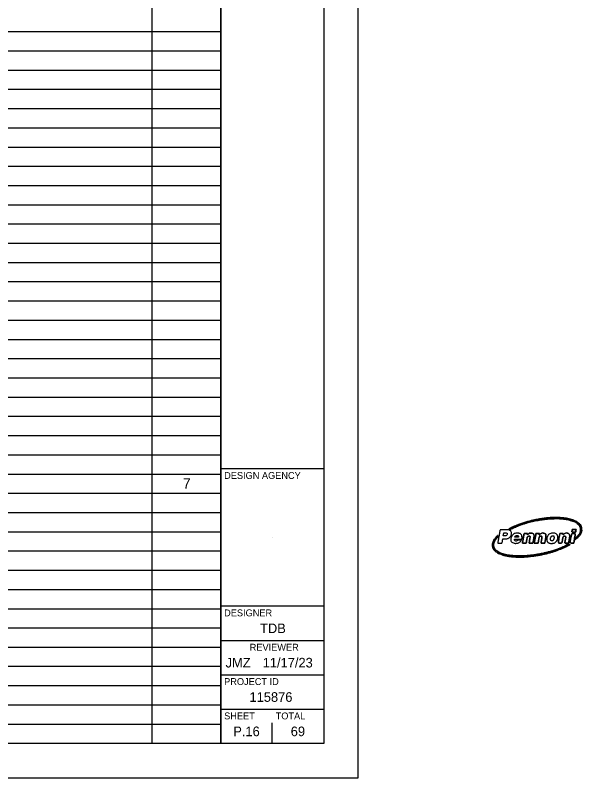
# Model space of a CAD drawing. Extents: x -31.7 to 37.3, y 0 to 22.
# Drawn here: x 29.01 to 37.25, y 0 to 11.1 of the extents above; entities that cross this region are included whole.
import ezdxf

# ---------------------------------------------------------------- set-up
doc = ezdxf.new("R2010")
doc.units = 0
for name, color, linetype in [('SH_Border', 7, 'Continuous'), ('SH_Cut_Line', 7, 'Continuous'), ('SH_Data', 7, 'Continuous'), ('SH_Text', 7, 'Continuous')]:
    doc.layers.add(name, color=color, linetype=linetype)

msp = doc.modelspace()

# ---------------------------------------------------------------- linework, layer by layer
at = {"layer": 'SH_Border'}
for p, q in [((32, 0.5), (32, 21.5)), ((32, 4.5), (33.5, 4.5)), ((36.333, 3.503), (36.282, 3.503)), ((32, 2.5), (33.5, 2.5)), ((32, 2), (33.5, 2)), ((32, 1.5), (33.5, 1.5)), ((32, 1), (33.5, 1))]:
    msp.add_line(p, q, dxfattribs=at)
msp.add_lwpolyline([(1.5, 21.5), (33.5, 21.5), (33.5, 0.5), (1.5, 0.5)], close=True, dxfattribs=at)
for points, degree in [([(36.192, 3.621), (36.198, 3.619), (36.204, 3.616), (36.211, 3.615), (36.213, 3.614), (36.215, 3.614), (36.217, 3.615), (36.246, 3.629), (36.274, 3.643), (36.303, 3.655), (36.345, 3.673), (36.387, 3.688), (36.43, 3.701), (36.472, 3.714), (36.514, 3.725), (36.557, 3.734), (36.597, 3.743), (36.637, 3.751), (36.678, 3.756), (36.709, 3.76), (36.741, 3.764), (36.774, 3.767), (36.799, 3.769), (36.824, 3.77), (36.849, 3.771), (36.904, 3.772), (36.959, 3.77), (37.014, 3.762), (37.044, 3.758), (37.073, 3.752), (37.101, 3.742), (37.137, 3.731), (37.171, 3.717), (37.199, 3.691), (37.214, 3.678), (37.225, 3.661), (37.231, 3.641), (37.235, 3.624), (37.237, 3.607), (37.234, 3.589), (37.23, 3.569), (37.221, 3.552), (37.208, 3.536), (37.196, 3.521), (37.182, 3.508), (37.167, 3.495), (37.166, 3.494), (37.164, 3.492), (37.164, 3.49), (37.162, 3.485), (37.161, 3.479), (37.16, 3.473), (37.16, 3.471), (37.16, 3.469), (37.159, 3.465), (37.183, 3.485), (37.206, 3.505), (37.225, 3.529), (37.234, 3.54), (37.241, 3.553), (37.246, 3.566), (37.253, 3.585), (37.253, 3.604), (37.251, 3.623), (37.247, 3.658), (37.232, 3.685), (37.205, 3.708), (37.182, 3.728), (37.154, 3.741), (37.125, 3.752), (37.088, 3.766), (37.049, 3.774), (37.01, 3.779), (36.975, 3.784), (36.94, 3.787), (36.905, 3.788), (36.848, 3.789), (36.792, 3.787), (36.736, 3.781), (36.705, 3.777), (36.674, 3.773), (36.643, 3.768), (36.598, 3.761), (36.553, 3.752), (36.509, 3.74), (36.449, 3.725), (36.389, 3.707), (36.331, 3.684), (36.29, 3.669), (36.25, 3.651), (36.211, 3.631), (36.205, 3.628), (36.199, 3.625), (36.192, 3.621)], 3), ([(36.192, 3.621), (36.199, 3.625), (36.205, 3.628), (36.211, 3.631), (36.25, 3.651), (36.29, 3.669), (36.331, 3.684), (36.389, 3.707), (36.449, 3.725), (36.509, 3.74), (36.553, 3.752), (36.598, 3.761), (36.643, 3.768), (36.674, 3.773), (36.705, 3.777), (36.736, 3.781), (36.792, 3.787), (36.848, 3.789), (36.905, 3.788), (36.94, 3.787), (36.975, 3.784), (37.01, 3.779), (37.049, 3.774), (37.088, 3.766), (37.125, 3.752), (37.154, 3.741), (37.182, 3.728), (37.205, 3.708), (37.232, 3.685), (37.247, 3.658), (37.251, 3.623), (37.253, 3.604), (37.253, 3.585), (37.246, 3.566), (37.241, 3.553), (37.234, 3.54), (37.225, 3.529), (37.206, 3.505), (37.183, 3.485), (37.159, 3.465), (37.16, 3.469), (37.16, 3.471), (37.16, 3.473), (37.161, 3.479), (37.162, 3.485), (37.164, 3.49), (37.164, 3.492), (37.166, 3.494), (37.167, 3.495), (37.182, 3.508), (37.196, 3.521), (37.208, 3.536), (37.221, 3.552), (37.23, 3.569), (37.234, 3.589), (37.237, 3.607), (37.235, 3.624), (37.231, 3.641), (37.225, 3.661), (37.214, 3.678), (37.199, 3.691), (37.171, 3.717), (37.137, 3.731), (37.101, 3.742), (37.073, 3.752), (37.044, 3.758), (37.014, 3.762), (36.959, 3.77), (36.904, 3.772), (36.849, 3.771), (36.824, 3.77), (36.799, 3.769), (36.774, 3.767), (36.741, 3.764), (36.709, 3.76), (36.678, 3.756), (36.637, 3.751), (36.597, 3.743), (36.557, 3.734), (36.514, 3.725), (36.472, 3.714), (36.43, 3.701), (36.387, 3.688), (36.345, 3.673), (36.303, 3.655), (36.274, 3.643), (36.246, 3.629), (36.217, 3.615), (36.215, 3.614), (36.213, 3.614), (36.211, 3.615), (36.204, 3.616), (36.198, 3.619), (36.192, 3.621)], 3), ([(36.203, 3.602), (36.19, 3.608), (36.177, 3.61), (36.163, 3.61), (36.131, 3.611), (36.1, 3.61), (36.068, 3.61), (36.066, 3.61), (36.065, 3.61), (36.065, 3.608), (36.061, 3.586), (36.057, 3.565), (36.053, 3.543), (36.047, 3.509), (36.041, 3.474), (36.035, 3.439), (36.034, 3.432), (36.033, 3.424), (36.031, 3.417)], 3), ([(36.105, 3.477), (36.112, 3.477), (36.119, 3.477), (36.126, 3.477), (36.139, 3.477), (36.152, 3.477), (36.165, 3.48), (36.181, 3.483), (36.196, 3.49), (36.208, 3.502), (36.223, 3.518), (36.229, 3.537), (36.23, 3.559), (36.23, 3.578), (36.221, 3.593), (36.203, 3.602)], 3), ([(36.112, 3.522), (36.115, 3.536), (36.117, 3.55), (36.12, 3.563), (36.12, 3.564), (36.121, 3.565), (36.122, 3.565), (36.133, 3.565), (36.145, 3.567), (36.156, 3.563), (36.167, 3.56), (36.17, 3.554), (36.168, 3.543)], 3), ([(36.384, 3.508), (36.38, 3.533), (36.367, 3.55), (36.343, 3.557), (36.33, 3.562), (36.317, 3.562), (36.303, 3.561), (36.281, 3.558), (36.262, 3.549), (36.247, 3.532), (36.233, 3.517), (36.225, 3.5), (36.222, 3.479), (36.219, 3.45), (36.232, 3.426), (36.261, 3.417), (36.277, 3.412), (36.293, 3.411), (36.309, 3.414), (36.327, 3.416), (36.343, 3.422), (36.357, 3.434), (36.365, 3.441), (36.371, 3.449), (36.376, 3.459)], 3), ([(36.39, 3.416), (36.391, 3.415), (36.391, 3.415), (36.392, 3.415), (36.409, 3.415), (36.426, 3.415), (36.443, 3.415), (36.445, 3.415), (36.446, 3.416), (36.446, 3.418), (36.448, 3.426), (36.449, 3.435), (36.45, 3.443), (36.453, 3.46), (36.456, 3.478), (36.46, 3.495), (36.462, 3.505), (36.467, 3.513), (36.477, 3.515), (36.49, 3.519), (36.503, 3.516), (36.501, 3.497), (36.499, 3.482), (36.497, 3.468), (36.494, 3.454), (36.492, 3.441), (36.49, 3.428), (36.487, 3.416), (36.488, 3.415), (36.489, 3.415), (36.489, 3.415), (36.506, 3.415), (36.523, 3.415), (36.54, 3.415), (36.543, 3.415), (36.543, 3.416), (36.544, 3.419), (36.548, 3.442), (36.552, 3.466), (36.556, 3.49), (36.558, 3.502), (36.561, 3.515), (36.559, 3.527), (36.557, 3.543), (36.547, 3.554), (36.532, 3.558), (36.51, 3.564), (36.49, 3.56), (36.473, 3.545), (36.469, 3.542), (36.466, 3.538), (36.462, 3.535), (36.463, 3.542), (36.464, 3.549), (36.465, 3.557), (36.449, 3.557), (36.433, 3.557), (36.417, 3.556), (36.416, 3.556), (36.415, 3.555), (36.414, 3.554), (36.413, 3.55), (36.413, 3.545), (36.412, 3.541), (36.407, 3.511), (36.401, 3.48), (36.396, 3.45), (36.394, 3.438), (36.392, 3.427), (36.39, 3.416)], 3), ([(36.39, 3.416), (36.392, 3.427), (36.394, 3.438), (36.396, 3.45), (36.401, 3.48), (36.407, 3.511), (36.412, 3.541), (36.413, 3.545), (36.413, 3.55), (36.414, 3.554), (36.415, 3.555), (36.416, 3.556), (36.417, 3.556), (36.433, 3.557), (36.449, 3.557), (36.465, 3.557), (36.464, 3.549), (36.463, 3.542), (36.462, 3.535), (36.466, 3.538), (36.469, 3.542), (36.473, 3.545), (36.49, 3.56), (36.51, 3.564), (36.532, 3.558), (36.547, 3.554), (36.557, 3.543), (36.559, 3.527), (36.561, 3.515), (36.558, 3.502), (36.556, 3.49), (36.552, 3.466), (36.548, 3.442), (36.544, 3.419), (36.543, 3.416), (36.543, 3.415), (36.54, 3.415), (36.523, 3.415), (36.506, 3.415), (36.489, 3.415), (36.489, 3.415), (36.488, 3.415), (36.487, 3.416), (36.49, 3.428), (36.492, 3.441), (36.494, 3.454), (36.497, 3.468), (36.499, 3.482), (36.501, 3.497), (36.503, 3.516), (36.49, 3.519), (36.477, 3.515), (36.467, 3.513), (36.462, 3.505), (36.46, 3.495), (36.456, 3.478), (36.453, 3.46), (36.45, 3.443), (36.449, 3.435), (36.448, 3.426), (36.446, 3.418), (36.446, 3.416), (36.445, 3.415), (36.443, 3.415), (36.426, 3.415), (36.409, 3.415), (36.392, 3.415), (36.391, 3.415), (36.391, 3.415), (36.39, 3.416)], 3), ([(36.563, 3.416), (36.564, 3.415), (36.564, 3.415), (36.564, 3.415), (36.581, 3.415), (36.599, 3.415), (36.616, 3.415), (36.617, 3.415), (36.619, 3.417), (36.619, 3.418), (36.622, 3.435), (36.625, 3.452), (36.628, 3.469), (36.63, 3.479), (36.632, 3.49), (36.635, 3.5), (36.639, 3.513), (36.651, 3.519), (36.664, 3.516), (36.67, 3.515), (36.673, 3.511), (36.674, 3.505), (36.674, 3.502), (36.675, 3.499), (36.674, 3.496), (36.672, 3.485), (36.671, 3.473), (36.669, 3.462), (36.666, 3.447), (36.663, 3.431), (36.661, 3.416), (36.661, 3.415), (36.661, 3.415), (36.661, 3.415), (36.679, 3.415), (36.696, 3.415), (36.714, 3.415), (36.715, 3.415), (36.716, 3.417), (36.716, 3.418), (36.72, 3.441), (36.725, 3.463), (36.728, 3.485), (36.73, 3.497), (36.732, 3.509), (36.732, 3.522), (36.732, 3.537), (36.726, 3.55), (36.711, 3.556), (36.69, 3.564), (36.67, 3.562), (36.652, 3.55), (36.646, 3.545), (36.641, 3.54), (36.635, 3.535), (36.636, 3.543), (36.637, 3.549), (36.638, 3.557), (36.622, 3.557), (36.606, 3.557), (36.59, 3.557), (36.587, 3.557), (36.587, 3.555), (36.587, 3.553), (36.583, 3.529), (36.579, 3.505), (36.575, 3.481), (36.571, 3.46), (36.567, 3.438), (36.563, 3.416)], 3), ([(36.563, 3.416), (36.567, 3.438), (36.571, 3.46), (36.575, 3.481), (36.579, 3.505), (36.583, 3.529), (36.587, 3.553), (36.587, 3.555), (36.587, 3.557), (36.59, 3.557), (36.606, 3.557), (36.622, 3.557), (36.638, 3.557), (36.637, 3.549), (36.636, 3.543), (36.635, 3.535), (36.641, 3.54), (36.646, 3.545), (36.652, 3.55), (36.67, 3.562), (36.69, 3.564), (36.711, 3.556), (36.726, 3.55), (36.732, 3.537), (36.732, 3.522), (36.732, 3.509), (36.73, 3.497), (36.728, 3.485), (36.725, 3.463), (36.72, 3.441), (36.716, 3.418), (36.716, 3.417), (36.715, 3.415), (36.714, 3.415), (36.696, 3.415), (36.679, 3.415), (36.661, 3.415), (36.661, 3.415), (36.661, 3.415), (36.661, 3.416), (36.663, 3.431), (36.666, 3.447), (36.669, 3.462), (36.671, 3.473), (36.672, 3.485), (36.674, 3.496), (36.675, 3.499), (36.674, 3.502), (36.674, 3.505), (36.673, 3.511), (36.67, 3.515), (36.664, 3.516), (36.651, 3.519), (36.639, 3.513), (36.635, 3.5), (36.632, 3.49), (36.63, 3.479), (36.628, 3.469), (36.625, 3.452), (36.622, 3.435), (36.619, 3.418), (36.619, 3.417), (36.617, 3.415), (36.616, 3.415), (36.599, 3.415), (36.581, 3.415), (36.564, 3.415), (36.564, 3.415), (36.564, 3.415), (36.563, 3.416)], 3), ([(36.906, 3.508), (36.905, 3.53), (36.894, 3.545), (36.873, 3.554), (36.854, 3.562), (36.834, 3.562), (36.814, 3.558), (36.79, 3.553), (36.771, 3.541), (36.758, 3.52), (36.757, 3.518), (36.755, 3.515), (36.754, 3.513), (36.753, 3.511), (36.752, 3.509), (36.751, 3.507), (36.746, 3.496), (36.744, 3.484), (36.743, 3.472), (36.743, 3.47), (36.743, 3.467), (36.743, 3.465), (36.744, 3.457), (36.745, 3.45), (36.748, 3.444), (36.749, 3.443), (36.749, 3.441), (36.75, 3.44), (36.75, 3.439), (36.751, 3.438), (36.752, 3.437), (36.754, 3.434), (36.757, 3.43), (36.76, 3.427), (36.762, 3.426), (36.764, 3.424), (36.766, 3.423), (36.767, 3.422), (36.767, 3.422), (36.768, 3.422), (36.769, 3.421), (36.77, 3.42), (36.772, 3.42), (36.773, 3.419), (36.775, 3.418), (36.777, 3.417), (36.788, 3.412), (36.8, 3.411), (36.812, 3.41)], 3), ([(36.934, 3.556), (36.926, 3.509), (36.917, 3.462), (36.909, 3.415), (36.928, 3.415), (36.946, 3.415), (36.965, 3.415), (36.967, 3.43), (36.97, 3.444), (36.972, 3.458), (36.974, 3.471), (36.977, 3.484), (36.979, 3.496), (36.983, 3.51), (36.992, 3.517), (37.006, 3.517), (37.014, 3.516), (37.019, 3.511), (37.02, 3.503), (37.021, 3.5), (37.021, 3.497), (37.02, 3.494), (37.017, 3.475), (37.014, 3.456), (37.01, 3.437), (37.009, 3.43), (37.008, 3.423), (37.007, 3.415), (37.025, 3.415), (37.044, 3.415), (37.062, 3.415), (37.062, 3.417), (37.063, 3.418), (37.063, 3.419), (37.067, 3.44), (37.07, 3.462), (37.074, 3.483), (37.076, 3.497), (37.079, 3.51), (37.078, 3.525), (37.077, 3.541), (37.068, 3.553), (37.053, 3.558), (37.028, 3.565), (37.006, 3.559), (36.987, 3.541), (36.985, 3.539), (36.983, 3.537), (36.982, 3.535), (36.981, 3.535), (36.981, 3.535), (36.981, 3.536), (36.982, 3.542), (36.983, 3.549), (36.984, 3.556), (36.967, 3.556), (36.951, 3.556), (36.934, 3.556)], 3), ([(36.934, 3.556), (36.951, 3.556), (36.967, 3.556), (36.984, 3.556), (36.983, 3.549), (36.982, 3.542), (36.981, 3.536), (36.981, 3.535), (36.981, 3.535), (36.982, 3.535), (36.983, 3.537), (36.985, 3.539), (36.987, 3.541), (37.006, 3.559), (37.028, 3.565), (37.053, 3.558), (37.068, 3.553), (37.077, 3.541), (37.078, 3.525), (37.079, 3.51), (37.076, 3.497), (37.074, 3.483), (37.07, 3.462), (37.067, 3.44), (37.063, 3.419), (37.063, 3.418), (37.062, 3.417), (37.062, 3.415), (37.044, 3.415), (37.025, 3.415), (37.007, 3.415), (37.008, 3.423), (37.009, 3.43), (37.01, 3.437), (37.014, 3.456), (37.017, 3.475), (37.02, 3.494), (37.021, 3.497), (37.021, 3.5), (37.02, 3.503), (37.019, 3.511), (37.014, 3.516), (37.006, 3.517), (36.992, 3.517), (36.983, 3.51), (36.979, 3.496), (36.977, 3.484), (36.974, 3.471), (36.972, 3.458), (36.97, 3.444), (36.967, 3.43), (36.965, 3.415), (36.946, 3.415), (36.928, 3.415), (36.909, 3.415), (36.917, 3.462), (36.926, 3.509), (36.934, 3.556)], 3), ([(37.137, 3.417), (37.118, 3.417), (37.1, 3.417), (37.081, 3.417), (37.09, 3.464), (37.098, 3.51), (37.106, 3.557), (37.124, 3.557), (37.142, 3.557), (37.161, 3.557), (37.153, 3.51), (37.145, 3.464), (37.137, 3.417)], 3), ([(37.137, 3.417), (37.145, 3.464), (37.153, 3.51), (37.161, 3.557), (37.142, 3.557), (37.124, 3.557), (37.106, 3.557), (37.098, 3.51), (37.09, 3.464), (37.081, 3.417), (37.1, 3.417), (37.118, 3.417), (37.137, 3.417)], 3), ([(37.171, 3.615), (37.169, 3.603), (37.167, 3.591), (37.165, 3.578), (37.165, 3.577), (37.163, 3.576), (37.162, 3.576), (37.145, 3.576), (37.127, 3.576), (37.109, 3.576), (37.111, 3.586), (37.112, 3.595), (37.114, 3.604), (37.114, 3.606), (37.115, 3.609), (37.115, 3.611), (37.115, 3.615), (37.117, 3.615), (37.12, 3.615), (37.136, 3.615), (37.151, 3.615), (37.167, 3.615), (37.168, 3.615), (37.17, 3.615), (37.171, 3.615)], 3), ([(37.171, 3.615), (37.17, 3.615), (37.168, 3.615), (37.167, 3.615), (37.151, 3.615), (37.136, 3.615), (37.12, 3.615), (37.117, 3.615), (37.115, 3.615), (37.115, 3.611), (37.115, 3.609), (37.114, 3.606), (37.114, 3.604), (37.112, 3.595), (37.111, 3.586), (37.109, 3.576), (37.127, 3.576), (37.145, 3.576), (37.162, 3.576), (37.163, 3.576), (37.165, 3.577), (37.165, 3.578), (37.167, 3.591), (37.169, 3.603), (37.171, 3.615)], 3), ([(37.08, 3.392), (37.08, 3.392), (37.08, 3.393), (37.079, 3.393), (37.069, 3.393), (37.06, 3.393), (37.05, 3.393), (37.047, 3.393), (37.044, 3.392), (37.042, 3.391), (37.005, 3.372), (36.967, 3.355), (36.928, 3.34), (36.87, 3.317), (36.811, 3.298), (36.75, 3.283), (36.707, 3.271), (36.664, 3.262), (36.62, 3.254), (36.595, 3.25), (36.571, 3.246), (36.546, 3.242), (36.52, 3.239), (36.495, 3.236), (36.469, 3.234), (36.445, 3.232), (36.421, 3.23), (36.396, 3.23), (36.368, 3.229), (36.34, 3.228), (36.312, 3.229), (36.281, 3.231), (36.25, 3.233), (36.219, 3.236), (36.181, 3.24), (36.144, 3.248), (36.107, 3.259), (36.075, 3.269), (36.045, 3.282), (36.019, 3.302), (36.002, 3.314), (35.988, 3.329), (35.979, 3.348), (35.966, 3.374), (35.968, 3.4), (35.978, 3.427), (35.987, 3.45), (36.002, 3.47), (36.018, 3.488), (36.024, 3.494), (36.029, 3.5), (36.03, 3.509), (36.03, 3.514), (36.031, 3.52), (36.033, 3.526), (36.031, 3.525), (36.03, 3.525), (36.03, 3.524), (36.02, 3.514), (36.01, 3.505), (36.001, 3.494), (35.982, 3.472), (35.966, 3.448), (35.958, 3.419), (35.953, 3.402), (35.952, 3.385), (35.955, 3.368), (35.96, 3.341), (35.974, 3.319), (35.994, 3.301), (36.016, 3.28), (36.043, 3.266), (36.071, 3.254), (36.119, 3.235), (36.168, 3.225), (36.218, 3.219), (36.249, 3.216), (36.28, 3.214), (36.311, 3.212), (36.353, 3.211), (36.396, 3.211), (36.438, 3.215), (36.472, 3.217), (36.506, 3.221), (36.54, 3.225), (36.571, 3.229), (36.602, 3.234), (36.632, 3.239), (36.687, 3.249), (36.74, 3.261), (36.793, 3.276), (36.839, 3.289), (36.883, 3.304), (36.927, 3.321), (36.97, 3.338), (37.012, 3.356), (37.053, 3.377), (37.062, 3.382), (37.071, 3.387), (37.08, 3.392)], 3), ([(37.08, 3.392), (37.071, 3.387), (37.062, 3.382), (37.053, 3.377), (37.012, 3.356), (36.97, 3.338), (36.927, 3.321), (36.883, 3.304), (36.839, 3.289), (36.793, 3.276), (36.74, 3.261), (36.687, 3.249), (36.632, 3.239), (36.602, 3.234), (36.571, 3.229), (36.54, 3.225), (36.506, 3.221), (36.472, 3.217), (36.438, 3.215), (36.396, 3.211), (36.353, 3.211), (36.311, 3.212), (36.28, 3.214), (36.249, 3.216), (36.218, 3.219), (36.168, 3.225), (36.119, 3.235), (36.071, 3.254), (36.043, 3.266), (36.016, 3.28), (35.994, 3.301), (35.974, 3.319), (35.96, 3.341), (35.955, 3.368), (35.952, 3.385), (35.953, 3.402), (35.958, 3.419), (35.966, 3.448), (35.982, 3.472), (36.001, 3.494), (36.01, 3.505), (36.02, 3.514), (36.03, 3.524), (36.03, 3.525), (36.031, 3.525), (36.033, 3.526), (36.031, 3.52), (36.03, 3.514), (36.03, 3.509), (36.029, 3.5), (36.024, 3.494), (36.018, 3.488), (36.002, 3.47), (35.987, 3.45), (35.978, 3.427), (35.968, 3.4), (35.966, 3.374), (35.979, 3.348), (35.988, 3.329), (36.002, 3.314), (36.019, 3.302), (36.045, 3.282), (36.075, 3.269), (36.107, 3.259), (36.144, 3.248), (36.181, 3.24), (36.219, 3.236), (36.25, 3.233), (36.281, 3.231), (36.312, 3.229), (36.34, 3.228), (36.368, 3.229), (36.396, 3.23), (36.421, 3.23), (36.445, 3.232), (36.469, 3.234), (36.495, 3.236), (36.52, 3.239), (36.546, 3.242), (36.571, 3.246), (36.595, 3.25), (36.62, 3.254), (36.664, 3.262), (36.707, 3.271), (36.75, 3.283), (36.811, 3.298), (36.87, 3.317), (36.928, 3.34), (36.967, 3.355), (37.005, 3.372), (37.042, 3.391), (37.044, 3.392), (37.047, 3.393), (37.05, 3.393), (37.06, 3.393), (37.069, 3.393), (37.079, 3.393), (37.08, 3.393), (37.08, 3.392), (37.08, 3.392)], 3), ([(36.031, 3.417), (36.032, 3.417), (36.033, 3.417), (36.033, 3.417), (36.053, 3.417), (36.072, 3.417), (36.092, 3.417), (36.094, 3.417), (36.094, 3.418), (36.095, 3.42), (36.097, 3.431), (36.099, 3.442), (36.101, 3.454), (36.102, 3.461), (36.103, 3.469), (36.105, 3.477)], 3), ([(36.168, 3.543), (36.166, 3.531), (36.157, 3.523), (36.145, 3.522), (36.134, 3.522), (36.124, 3.522), (36.112, 3.522)], 3), ([(36.376, 3.459), (36.358, 3.459), (36.342, 3.459), (36.325, 3.458), (36.324, 3.458), (36.323, 3.457), (36.321, 3.457), (36.317, 3.454), (36.314, 3.45), (36.309, 3.448), (36.293, 3.442), (36.276, 3.451), (36.276, 3.47), (36.276, 3.474), (36.278, 3.475), (36.281, 3.475), (36.314, 3.475), (36.346, 3.475), (36.378, 3.475), (36.38, 3.475), (36.381, 3.475), (36.383, 3.475)], 3), ([(36.282, 3.503), (36.283, 3.515), (36.293, 3.525), (36.305, 3.527), (36.311, 3.528), (36.317, 3.528), (36.323, 3.525), (36.33, 3.521), (36.334, 3.513), (36.333, 3.503)], 3), ([(36.383, 3.475), (36.385, 3.486), (36.386, 3.497), (36.384, 3.508)], 2), ([(36.799, 3.471), (36.8, 3.487), (36.802, 3.501), (36.811, 3.513), (36.816, 3.519), (36.823, 3.523), (36.831, 3.523), (36.84, 3.523), (36.846, 3.52), (36.848, 3.511), (36.85, 3.505), (36.85, 3.498), (36.85, 3.491)], 3), ([(36.85, 3.491), (36.849, 3.481), (36.846, 3.471), (36.841, 3.462), (36.835, 3.452), (36.826, 3.447), (36.815, 3.449), (36.808, 3.45), (36.804, 3.453), (36.802, 3.459), (36.8, 3.464), (36.8, 3.469), (36.799, 3.471)], 3), ([(36.812, 3.41), (36.819, 3.411), (36.826, 3.412), (36.833, 3.413), (36.853, 3.416), (36.869, 3.425), (36.883, 3.439), (36.9, 3.459), (36.907, 3.482), (36.906, 3.508)], 3)]:
    msp.add_open_spline(points, degree=degree, dxfattribs=at)
at = {"layer": 'SH_Cut_Line'}
msp.add_lwpolyline([(0, 0), (34, 0), (34, 22), (0, 22)], close=True, dxfattribs=at)
at = {"layer": 'SH_Data'}
for p, q in [((30.997, 21.5), (30.997, 0.502)), ((32.001, 21.5), (32.001, 0.502)), ((1.5, 10.861), (32.001, 10.861)), ((1.5, 10.581), (32.001, 10.581)), ((1.5, 10.301), (32.001, 10.301)), ((1.5, 10.021), (32.001, 10.021)), ((1.5, 9.741), (32.001, 9.741)), ((1.5, 9.461), (32.001, 9.461)), ((1.5, 9.181), (32.001, 9.181)), ((1.5, 8.901), (32.001, 8.901)), ((1.5, 8.621), (32.001, 8.621)), ((1.5, 8.341), (32.001, 8.341)), ((1.5, 8.061), (32.001, 8.061)), ((1.5, 7.781), (32.001, 7.781)), ((1.5, 7.501), (32.001, 7.501)), ((1.5, 7.221), (32.001, 7.221)), ((1.5, 6.941), (32.001, 6.941)), ((1.5, 6.661), (32.001, 6.661)), ((1.5, 6.381), (32.001, 6.381)), ((1.5, 6.101), (32.001, 6.101)), ((1.5, 5.821), (32.001, 5.821)), ((1.5, 5.541), (32.001, 5.541)), ((1.5, 5.261), (32.001, 5.261)), ((1.5, 4.981), (32.001, 4.981)), ((1.5, 4.701), (32.001, 4.701)), ((1.5, 4.421), (32.001, 4.421)), ((1.5, 4.141), (32.001, 4.141)), ((1.5, 3.861), (32.001, 3.861)), ((1.5, 3.581), (32.001, 3.581)), ((32.75, 3.5), (32.75, 3.5)), ((1.5, 3.301), (32.001, 3.301)), ((1.5, 3.021), (32.001, 3.021)), ((1.5, 2.741), (32.001, 2.741)), ((1.5, 2.461), (32.001, 2.461)), ((1.5, 2.182), (32.001, 2.182)), ((1.5, 1.902), (32.001, 1.902)), ((1.5, 1.622), (32.001, 1.622)), ((1.5, 1.342), (32.001, 1.342)), ((1.5, 1.062), (32.001, 1.062)), ((1.5, 0.782), (32.001, 0.782)), ((32.75, 0.5), (32.75, 0.8)), ((32.375, 0.675), (32.375, 0.675)), ((1.5, 0.502), (32.001, 0.502))]:
    msp.add_line(p, q, dxfattribs=at)

# ---------------------------------------------------------------- texts
for s, height, p in [('DESIGN AGENCY', 0.1, (32.05, 4.35)), ('DESIGNER', 0.1, (32.05, 2.35)), ('TDB', 0.14, (32.573, 2.105)), ('REVIEWER', 0.1, (32.422, 1.85)), ('JMZ', 0.14, (32.071, 1.605)), ('11/17/23', 0.14, (32.611, 1.605)), ('PROJECT ID', 0.1, (32.05, 1.35)), ('115876', 0.14, (32.419, 1.105)), ('SHEET', 0.1, (32.05, 0.85)), ('TOTAL', 0.1, (32.8, 0.85)), ('P.16', 0.14, (32.183, 0.605)), ('69', 0.14, (33.019, 0.605))]:
    msp.add_text(s, height=height, dxfattribs=at).set_placement(p)
at = {"layer": 'SH_Text'}
msp.add_text('7', height=0.152, dxfattribs=at).set_placement((31.449, 4.206))

doc.saveas('drawing.dxf')
